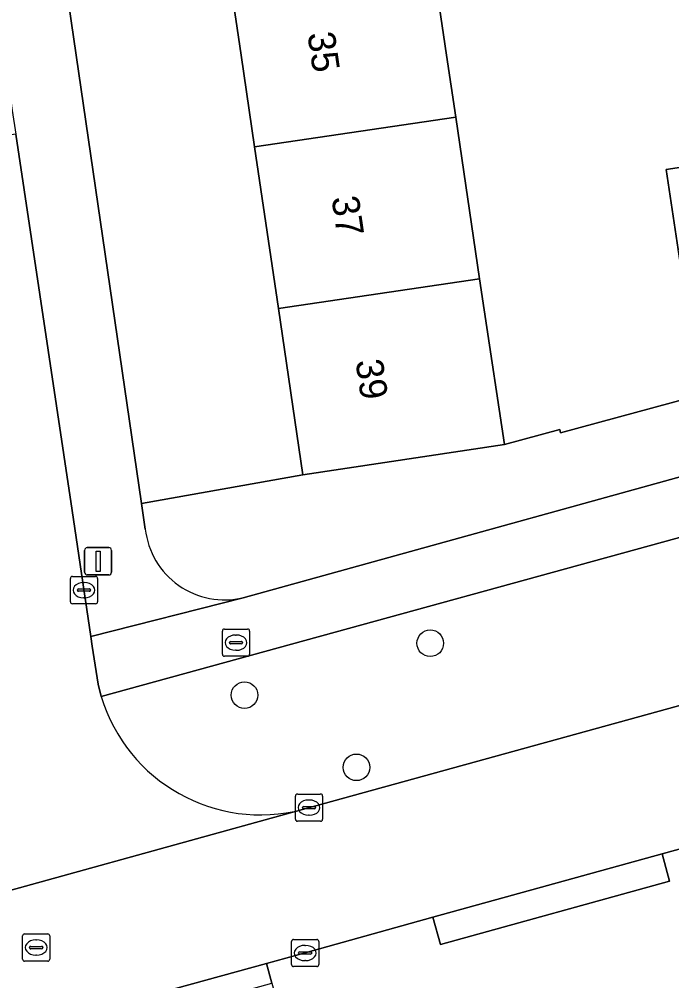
# Model space of a CAD drawing. Extents: x 159053 to 160042, y 380449 to 381423.
# Drawn here: x 159396.8 to 159420.77, y 380966 to 381001.32 of the extents above; entities that cross this region are included whole.
import ezdxf

# ---------------------------------------------------------------- set-up
doc = ezdxf.new("R2010")
doc.units = 0
for name, color, linetype in [('IMGEO_Berm_groen', 7, 'Continuous'), ('IMGEO_Boom', 7, 'Continuous'), ('IMGEO_Brandkraan', 7, 'Continuous'), ('IMGEO_Erf', 7, 'Continuous'), ('IMGEO_Groenvoorziening', 7, 'Continuous'), ('IMGEO_Kolk', 7, 'Continuous'), ('IMGEO_Lichtmast', 7, 'Continuous'), ('IMGEO_Pand', 7, 'Continuous'), ('IMGEO_Pand_nummerreeks', 7, 'Continuous'), ('IMGEO_Rijbaan_lokaal_open', 7, 'Continuous'), ('IMGEO_Rioolput', 7, 'Continuous'), ('IMGEO_Voetpad_open', 7, 'Continuous')]:
    doc.layers.add(name, color=color, linetype=linetype)

msp = doc.modelspace()

# ---------------------------------------------------------------- linework, layer by layer
at = {"layer": 'IMGEO_Berm_groen'}
for points in [[(159427.679, 380977.936), (159426.442, 380983.759), (159399.81, 380976.439)], [(159407.199, 380972.295), (159427.679, 380977.936)]]:
    msp.add_lwpolyline(points, dxfattribs=at)
msp.add_arc((159405.661, 380978.212), 6.114, 196.8601, 284.5696, dxfattribs=at)
at = {"layer": 'IMGEO_Boom'}
for centre in [(159411.897, 380978.399), (159405.073, 380976.496), (159409.185, 380973.842)]:
    msp.add_circle(centre, 0.489, dxfattribs=at)
at = {"layer": 'IMGEO_Brandkraan'}
for p, q in [((159404.333, 380978.922), (159405.185, 380978.922)), ((159404.258, 380977.996), (159404.258, 380978.848)), ((159404.746, 380978.702), (159404.771, 380978.702)), ((159405.259, 380978.848), (159405.259, 380977.996)), ((159404.517, 380978.416), (159404.517, 380978.428)), ((159404.955, 380978.379), (159404.557, 380978.379)), ((159404.56, 380978.465), (159404.958, 380978.465)), ((159405.001, 380978.428), (159405.001, 380978.416)), ((159405.185, 380977.922), (159404.333, 380977.922)), ((159404.769, 380978.142), (159404.744, 380978.142))]:
    msp.add_line(p, q, dxfattribs=at)
for points in [[(159404.333, 380978.922), (159405.185, 380978.922)], [(159404.258, 380977.996), (159404.258, 380978.848)], [(159405.259, 380978.848), (159405.259, 380977.996)], [(159405.185, 380977.922), (159404.333, 380977.922)]]:
    msp.add_lwpolyline(points, dxfattribs=at)
for centre, radius, start, end in [((159404.335, 380978.846), 0.0765, 91.552, 178.448), ((159404.335, 380978.846), 0.0765, 91.552, 178.448), ((159405.183, 380978.846), 0.0765, 1.552, 88.448), ((159405.183, 380978.846), 0.0765, 1.552, 88.448), ((159404.557, 380978.425), 0.0403, 85.8775, 175.7526), ((159404.554, 380978.415), 0.0366, 178.938, 274.7102), ((159404.958, 380978.422), 0.043, 264.8664, 352.4533), ((159404.962, 380978.427), 0.0386, 1.7309, 96.639), ((159404.335, 380977.998), 0.0765, 181.552, 268.448), ((159404.335, 380977.998), 0.0765, 181.552, 268.448), ((159405.183, 380977.998), 0.0765, 271.552, 358.448), ((159405.183, 380977.998), 0.0765, 271.552, 358.448)]:
    msp.add_arc(centre, radius, start, end, dxfattribs=at)
for centre, major_axis, ratio, start_param, end_param in [((159404.745, 380978.422), (-0.387, 0.002), 0.722429, 4.712389, 7.853982), ((159404.77, 380978.422), (-0.39, 0.002), 0.717154, 1.570796, 4.712389)]:
    msp.add_ellipse(centre, major_axis=major_axis, ratio=ratio, start_param=start_param, end_param=end_param, dxfattribs=at)
at = {"layer": 'IMGEO_Erf'}
for points in [[(159386.52, 381084.815), (159398.888, 381000), (159401.289, 380983.538), (159407.214, 380984.584), (159406.316, 380990.699), (159405.443, 380996.635), (159404.949, 381000), (159404.571, 381002.571), (159403.699, 381008.508), (159402.826, 381014.444), (159401.954, 381020.38), (159401.055, 381026.497), (159402.8, 381026.752), (159402.368, 381029.705), (159401.936, 381032.662), (159400.109, 381032.395), (159399.195, 381038.639)], [(159411.953, 381003.656), (159412.494, 381000), (159412.831, 380997.721), (159413.709, 380991.786), (159413.878, 380990.64), (159414.62, 380985.695), (159416.659, 380986.246), (159416.684, 380986.131), (159425.664, 380988.567), (159425.452, 380990.805), (159421.407, 380990.198), (159421.008, 380992.859), (159420.566, 380995.801), (159424.611, 380996.408), (159423.727, 381002.15)]]:
    msp.add_lwpolyline(points, dxfattribs=at)
at = {"layer": 'IMGEO_Groenvoorziening'}
msp.add_lwpolyline([(159405.022, 380980.072), (159426.077, 380985.889), (159425.664, 380988.567), (159416.684, 380986.131), (159416.659, 380986.246), (159414.62, 380985.695), (159407.214, 380984.584), (159401.289, 380983.538), (159401.426, 380982.595)], dxfattribs=at)
msp.add_arc((159404.339, 380982.922), 2.931, 186.4078, 283.4842, dxfattribs=at)
at = {"layer": 'IMGEO_Kolk'}
for p, q in [((159398.674, 380979.925), (159398.674, 380980.777)), ((159398.749, 380980.851), (159399.601, 380980.851)), ((159399.675, 380980.777), (159399.675, 380979.925)), ((159398.933, 380980.345), (159398.933, 380980.357)), ((159399.371, 380980.308), (159398.973, 380980.308)), ((159398.976, 380980.394), (159399.374, 380980.394)), ((159399.162, 380980.631), (159399.187, 380980.631)), ((159399.417, 380980.357), (159399.417, 380980.345)), ((159399.185, 380980.071), (159399.16, 380980.071)), ((159399.601, 380979.851), (159398.749, 380979.851)), ((159406.941, 380971.937), (159406.941, 380972.789)), ((159407.016, 380972.863), (159407.868, 380972.863)), ((159407.429, 380972.643), (159407.454, 380972.643)), ((159407.942, 380972.789), (159407.942, 380971.937)), ((159407.2, 380972.357), (159407.2, 380972.369)), ((159407.638, 380972.32), (159407.24, 380972.32)), ((159407.243, 380972.406), (159407.641, 380972.406)), ((159407.684, 380972.369), (159407.684, 380972.357)), ((159407.868, 380971.863), (159407.016, 380971.863)), ((159407.452, 380972.083), (159407.427, 380972.083)), ((159406.8, 380966.597), (159406.8, 380967.449)), ((159406.875, 380967.523), (159407.727, 380967.523)), ((159407.288, 380967.303), (159407.313, 380967.303)), ((159407.801, 380967.449), (159407.801, 380966.597)), ((159407.059, 380967.017), (159407.059, 380967.029)), ((159407.497, 380966.98), (159407.099, 380966.98)), ((159407.102, 380967.066), (159407.5, 380967.066)), ((159407.543, 380967.029), (159407.543, 380967.017)), ((159407.311, 380966.743), (159407.286, 380966.743)), ((159407.727, 380966.523), (159406.875, 380966.523))]:
    msp.add_line(p, q, dxfattribs=at)
for points in [[(159398.674, 380979.925), (159398.674, 380980.777)], [(159398.749, 380980.851), (159399.601, 380980.851)], [(159399.675, 380980.777), (159399.675, 380979.925)], [(159399.601, 380979.851), (159398.749, 380979.851)], [(159406.941, 380971.937), (159406.941, 380972.789)], [(159407.016, 380972.863), (159407.868, 380972.863)], [(159407.942, 380972.789), (159407.942, 380971.937)], [(159407.868, 380971.863), (159407.016, 380971.863)], [(159406.8, 380966.597), (159406.8, 380967.449)], [(159406.875, 380967.523), (159407.727, 380967.523)], [(159407.801, 380967.449), (159407.801, 380966.597)], [(159407.727, 380966.523), (159406.875, 380966.523)]]:
    msp.add_lwpolyline(points, dxfattribs=at)
for centre, radius, start, end in [((159398.751, 380980.775), 0.0765, 91.552, 178.448), ((159398.751, 380980.775), 0.0765, 91.552, 178.448), ((159399.599, 380980.775), 0.0765, 1.552, 88.448), ((159399.599, 380980.775), 0.0765, 1.552, 88.448), ((159398.973, 380980.354), 0.0403, 85.8775, 175.7526), ((159398.97, 380980.344), 0.0366, 178.938, 274.7102), ((159399.374, 380980.351), 0.043, 264.8664, 352.4533), ((159399.378, 380980.356), 0.0386, 1.7309, 96.639), ((159398.751, 380979.927), 0.0765, 181.552, 268.448), ((159398.751, 380979.927), 0.0765, 181.552, 268.448), ((159399.599, 380979.927), 0.0765, 271.552, 358.448), ((159399.599, 380979.927), 0.0765, 271.552, 358.448), ((159407.018, 380972.787), 0.0765, 91.552, 178.448), ((159407.018, 380972.787), 0.0765, 91.552, 178.448), ((159407.866, 380972.787), 0.0765, 1.552, 88.448), ((159407.866, 380972.787), 0.0765, 1.552, 88.448), ((159407.24, 380972.366), 0.0403, 85.8775, 175.7526), ((159407.237, 380972.356), 0.0366, 178.938, 274.7102), ((159407.641, 380972.363), 0.043, 264.8664, 352.4533), ((159407.645, 380972.368), 0.0386, 1.7309, 96.639), ((159407.018, 380971.939), 0.0765, 181.552, 268.448), ((159407.018, 380971.939), 0.0765, 181.552, 268.448), ((159407.866, 380971.939), 0.0765, 271.552, 358.448), ((159407.866, 380971.939), 0.0765, 271.552, 358.448), ((159406.877, 380967.447), 0.0765, 91.552, 178.448), ((159406.877, 380967.447), 0.0765, 91.552, 178.448), ((159407.725, 380967.447), 0.0765, 1.552, 88.448), ((159407.725, 380967.447), 0.0765, 1.552, 88.448), ((159407.099, 380967.026), 0.0403, 85.8775, 175.7526), ((159407.096, 380967.016), 0.0366, 178.938, 274.7102), ((159407.5, 380967.023), 0.043, 264.8664, 352.4533), ((159407.504, 380967.028), 0.0386, 1.7309, 96.639), ((159406.877, 380966.599), 0.0765, 181.552, 268.448), ((159406.877, 380966.599), 0.0765, 181.552, 268.448), ((159407.725, 380966.599), 0.0765, 271.552, 358.448), ((159407.725, 380966.599), 0.0765, 271.552, 358.448)]:
    msp.add_arc(centre, radius, start, end, dxfattribs=at)
for centre, major_axis, ratio, start_param, end_param in [((159399.161, 380980.351), (-0.387, 0.002), 0.722429, 4.712389, 7.853982), ((159399.186, 380980.351), (-0.39, 0.002), 0.717154, 1.570796, 4.712389), ((159407.428, 380972.363), (-0.387, 0.002), 0.722429, 4.712389, 7.853982), ((159407.453, 380972.363), (-0.39, 0.002), 0.717154, 1.570796, 4.712389), ((159407.287, 380967.023), (-0.387, 0.002), 0.722429, 4.712389, 7.853982), ((159407.312, 380967.023), (-0.39, 0.002), 0.717154, 1.570796, 4.712389)]:
    msp.add_ellipse(centre, major_axis=major_axis, ratio=ratio, start_param=start_param, end_param=end_param, dxfattribs=at)
at = {"layer": 'IMGEO_Lichtmast'}
for p, q in [((159399.197, 380981.01), (159399.197, 380981.81)), ((159399.197, 380981.81), (159399.197, 380981.01)), ((159399.297, 380981.91), (159400.087, 380981.91)), ((159400.087, 380981.91), (159399.297, 380981.91)), ((159400.187, 380981.81), (159400.187, 380981.01)), ((159400.187, 380981.01), (159400.187, 380981.81)), ((159400.087, 380980.91), (159399.297, 380980.91)), ((159399.297, 380980.91), (159400.087, 380980.91))]:
    msp.add_line(p, q, dxfattribs=at)
msp.add_lwpolyline([(159399.617, 380981.785), (159399.767, 380981.785), (159399.767, 380981.035), (159399.617, 380981.035), (159399.617, 380981.785)], dxfattribs=at)
for centre, start, end in [((159399.297, 380981.81), 90, 180), ((159399.297, 380981.81), 90, 180), ((159400.087, 380981.81), 0, 90), ((159400.087, 380981.81), 360, 90), ((159399.297, 380981.01), 180, 270), ((159399.297, 380981.01), 180, 270), ((159400.087, 380981.01), 270, 0), ((159400.087, 380981.01), 270, 0)]:
    msp.add_arc(centre, 0.1, start, end, dxfattribs=at)
at = {"layer": 'IMGEO_Pand'}
for points in [[(159411.953, 381003.656), (159404.571, 381002.571), (159404.949, 381000), (159405.443, 380996.635), (159412.831, 380997.721), (159412.494, 381000)], [(159405.443, 380996.635), (159406.316, 380990.699), (159413.709, 380991.786), (159412.831, 380997.721)], [(159425.054, 380993.454), (159424.611, 380996.408), (159420.566, 380995.801), (159421.008, 380992.859)], [(159406.316, 380990.699), (159407.214, 380984.584), (159414.62, 380985.695), (159413.878, 380990.64), (159413.709, 380991.786)]]:
    msp.add_lwpolyline(points, close=True, dxfattribs=at)
at = {"layer": 'IMGEO_Rijbaan_lokaal_open'}
for points in [[(159399.81, 380976.439), (159399.691, 380976.895), (159399.477, 380978.287), (159399.423, 380978.652), (159398.743, 380983.277), (159396.672, 380997.098), (159389.737, 380996.062), (159392.402, 380978.279), (159392.726, 380976.187), (159393.059, 380974.243)], [(159388.428, 380967.108), (159407.199, 380972.295)]]:
    msp.add_lwpolyline(points, dxfattribs=at)
msp.add_lwpolyline([(159411.991, 380968.337), (159420.412, 380970.666), (159424.234, 380971.723), (159430.149, 380973.358), (159428.84, 380978.256), (159427.679, 380977.936), (159407.199, 380972.295), (159388.428, 380967.108), (159370.309, 380963.188), (159371.327, 380958.167), (159387.418, 380961.568), (159405.884, 380966.636), (159407.297, 380967.024)], close=True, dxfattribs=at)
msp.add_arc((159405.661, 380978.212), 6.114, 196.8601, 284.5696, dxfattribs=at)
at = {"layer": 'IMGEO_Rioolput'}
for p, q in [((159396.918, 380966.798), (159396.918, 380967.65)), ((159396.993, 380967.724), (159397.845, 380967.724)), ((159397.919, 380967.65), (159397.919, 380966.798)), ((159397.22, 380967.267), (159397.618, 380967.267)), ((159397.406, 380967.504), (159397.431, 380967.504)), ((159397.177, 380967.218), (159397.177, 380967.23)), ((159397.615, 380967.181), (159397.217, 380967.181)), ((159397.429, 380966.944), (159397.404, 380966.944)), ((159397.661, 380967.23), (159397.661, 380967.218)), ((159397.845, 380966.724), (159396.993, 380966.724))]:
    msp.add_line(p, q, dxfattribs=at)
for points in [[(159396.918, 380966.798), (159396.918, 380967.65)], [(159396.993, 380967.724), (159397.845, 380967.724)], [(159397.919, 380967.65), (159397.919, 380966.798)], [(159397.845, 380966.724), (159396.993, 380966.724)]]:
    msp.add_lwpolyline(points, dxfattribs=at)
for centre, radius, start, end in [((159396.995, 380967.648), 0.0765, 91.552, 178.448), ((159396.995, 380967.648), 0.0765, 91.552, 178.448), ((159397.843, 380967.648), 0.0765, 1.552, 88.448), ((159397.843, 380967.648), 0.0765, 1.552, 88.448), ((159397.217, 380967.227), 0.0403, 85.8775, 175.7526), ((159397.622, 380967.229), 0.0386, 1.7309, 96.639), ((159397.214, 380967.217), 0.0366, 178.938, 274.7102), ((159397.618, 380967.224), 0.043, 264.8664, 352.4533), ((159396.995, 380966.8), 0.0765, 181.552, 268.448), ((159396.995, 380966.8), 0.0765, 181.552, 268.448), ((159397.843, 380966.8), 0.0765, 271.552, 358.448), ((159397.843, 380966.8), 0.0765, 271.552, 358.448)]:
    msp.add_arc(centre, radius, start, end, dxfattribs=at)
for centre, major_axis, ratio, start_param, end_param in [((159397.405, 380967.224), (-0.387, 0.002), 0.722429, 4.712389, 7.853982), ((159397.43, 380967.224), (-0.39, 0.002), 0.717154, 1.570796, 4.712389)]:
    msp.add_ellipse(centre, major_axis=major_axis, ratio=ratio, start_param=start_param, end_param=end_param, dxfattribs=at)
at = {"layer": 'IMGEO_Voetpad_open'}
for points in [[(159379.085, 381116.801), (159379.229, 381115.714), (159381.855, 381098.856), (159382.253, 381096.095), (159383.303, 381088.805), (159385.799, 381072.168), (159389.532, 381045.961), (159389.922, 381043.228), (159390.597, 381038.488), (159396.262, 380999.919), (159396.542, 380997.966), (159396.672, 380997.098), (159398.743, 380983.277), (159399.423, 380978.652), (159405.022, 380980.072)], [(159398.888, 381000), (159386.52, 381084.815)], [(159401.426, 380982.595), (159401.289, 380983.538), (159398.888, 381000)], [(159453.588, 380990.672), (159453.189, 380993.369), (159447.546, 380991.822), (159427.248, 380986.213), (159427.041, 380989.114), (159425.664, 380988.567), (159426.077, 380985.889), (159405.022, 380980.072), (159399.423, 380978.652), (159399.477, 380978.287), (159399.691, 380976.895), (159399.81, 380976.439), (159426.442, 380983.759), (159427.679, 380977.936), (159428.84, 380978.256), (159429.341, 380978.394), (159428.187, 380984.259)], [(159422.944, 380968.402), (159424.993, 380968.961), (159424.414, 380971), (159424.234, 380971.723), (159420.412, 380970.666), (159420.689, 380969.664), (159412.268, 380967.335), (159411.991, 380968.337), (159407.297, 380967.024), (159405.884, 380966.636), (159406.074, 380965.914), (159406.59, 380964.068), (159408.965, 380964.525)], [(159338.456, 380950.454), (159387.057, 380960.735), (159388.31, 380961), (159406.074, 380965.914), (159405.884, 380966.636), (159387.418, 380961.568), (159371.327, 380958.167), (159368.653, 380957.602), (159365.297, 380956.893), (159346.137, 380952.833), (159329.58, 380949.342), (159325.526, 380948.22)]]:
    msp.add_lwpolyline(points, dxfattribs=at)
msp.add_lwpolyline([(159420.412, 380970.666), (159411.991, 380968.337), (159412.268, 380967.335), (159420.689, 380969.664)], close=True, dxfattribs=at)
msp.add_arc((159404.339, 380982.922), 2.931, 186.4078, 283.4842, dxfattribs=at)

# ---------------------------------------------------------------- texts
at = {"layer": 'IMGEO_Pand_nummerreeks'}
for s, rotation, p in [('35', 278.357, (159407.381, 381000.787)), ('37', 278.3587, (159408.266, 380994.761)), ('39', 278.3587, (159409.147, 380988.765))]:
    msp.add_text(s, height=1, rotation=rotation, dxfattribs=at).set_placement(p)

doc.saveas('drawing.dxf')
